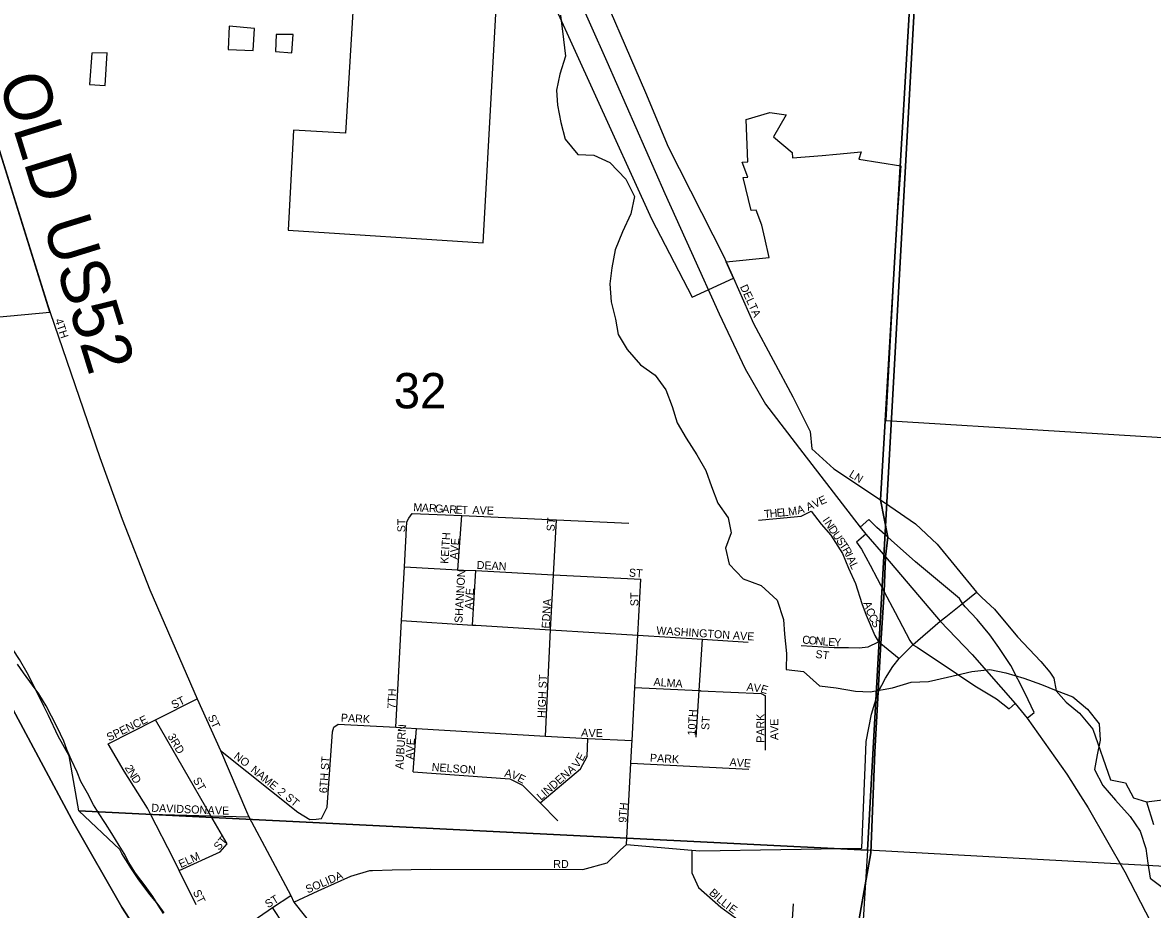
# Model space of a CAD drawing. Extents: x 0 to 34, y 0 to 22.
# Drawn here: x 3.579 to 4.916, y 15.917 to 16.966 of the extents above; entities that cross this region are included whole.
import ezdxf

# ---------------------------------------------------------------- set-up
doc = ezdxf.new("R2010")
doc.units = 0
for name, color, linetype in [('GM_X_City_Street', 7, 'Continuous'), ('GM_X_City_Street_Text', 7, 'Continuous'), ('GM_X_Corporation', 7, 'Continuous'), ('GM_X_County', 7, 'Continuous'), ('GM_X_County_Road', 7, 'Continuous'), ('GM_X_County_Road_Text', 7, 'Continuous'), ('GM_X_Interchange_Ramps', 7, 'Continuous'), ('GM_X_Major_River', 7, 'Continuous'), ('GM_X_Minor_River', 7, 'Continuous'), ('GM_X_Section', 7, 'Continuous'), ('GM_X_Section_Text', 7, 'Continuous'), ('GM_X_Township', 7, 'Continuous'), ('GM_X_US_Route', 7, 'Continuous')]:
    doc.layers.add(name, color=color, linetype=linetype)

msp = doc.modelspace()

# ---------------------------------------------------------------- linework, layer by layer
at = {"layer": 'GM_X_City_Street'}
for points in [[(4.4171, 16.6712), (4.4203, 16.6641), (4.444, 16.6102), (4.4906, 16.5234), (4.5111, 16.4824), (4.513, 16.4617), (4.5391, 16.4381), (4.5943, 16.4014), (4.6054, 16.394), (4.6357, 16.3731), (4.6611, 16.3492), (4.7078, 16.2921)], [(3.6089, 16.6314), (3.6115, 16.6232), (3.6703, 16.4516), (3.6969, 16.3788), (3.7295, 16.2949), (3.7856, 16.1658), (3.8131, 16.1047), (3.844, 16.0324)], [(4.0236, 16.191), (4.0236, 16.1911), (4.0273, 16.2587), (4.0308, 16.3221), (4.0338, 16.3753), (4.0361, 16.3799), (4.0399, 16.3855)], [(4.0399, 16.3855), (4.0794, 16.3837), (4.0794, 16.3837)], [(4.0794, 16.3837), (4.0987, 16.3829), (4.2108, 16.3779), (4.2965, 16.374)], [(4.094, 16.3188), (4.0987, 16.3829)], [(4.4497, 16.3775), (4.471, 16.3795)], [(4.471, 16.3795), (4.5002, 16.3823), (4.5123, 16.388)], [(4.5123, 16.388), (4.5241, 16.3729), (4.5352, 16.3595), (4.5491, 16.338), (4.5564, 16.3208), (4.5647, 16.3025), (4.5722, 16.2788), (4.5773, 16.265), (4.5876, 16.2408), (4.5917, 16.2336), (4.5946, 16.2313), (4.6163, 16.2137)], [(4.2036, 16.2475), (4.2072, 16.3128), (4.2108, 16.3779)], [(4.7142, 16.2859), (4.7289, 16.2719), (4.7564, 16.2394), (4.784, 16.21), (4.7944, 16.1975), (4.7992, 16.1905), (4.8021, 16.1756), (4.8137, 16.1619), (4.8296, 16.149), (4.8455, 16.13), (4.8663, 16.0699), (4.8842, 16.0666), (4.8936, 16.0489), (4.909, 16.0441), (4.9279, 16.0462), (4.9395, 16.0544), (4.958, 16.0642), (4.9762, 16.0851), (4.9804, 16.1117), (4.9849, 16.1577), (4.9906, 16.174), (5.0084, 16.2067), (5.094, 16.3278), (5.0961, 16.3307)], [(4.0308, 16.3221), (4.094, 16.3188), (4.1007, 16.3184)], [(4.1007, 16.3184), (4.1007, 16.3184), (4.1153, 16.3177), (4.2072, 16.3128), (4.3105, 16.3074)], [(4.1112, 16.2533), (4.1153, 16.3177)], [(4.2999, 16.1113), (4.3002, 16.1166), (4.3036, 16.1793), (4.3069, 16.2412), (4.3105, 16.3074)], [(4.6913, 16.2786), (4.7078, 16.2921), (4.7142, 16.2859)], [(4.6714, 16.2631), (4.6913, 16.2786)], [(4.5764, 16.0946), (4.5772, 16.1154), (4.5834, 16.1478), (4.5915, 16.174), (4.6002, 16.1905), (4.6087, 16.2042), (4.6163, 16.2137), (4.6283, 16.2261), (4.6326, 16.2298), (4.6648, 16.2579), (4.6714, 16.2631)], [(4.0273, 16.2587), (4.1112, 16.2533), (4.115, 16.2531), (4.1152, 16.2531)], [(4.1152, 16.2531), (4.2036, 16.2475), (4.3069, 16.2412), (4.3835, 16.2365), (4.4374, 16.2332)], [(4.1977, 16.1219), (4.2036, 16.2475)], [(4.3761, 16.1207), (4.3796, 16.1757), (4.3835, 16.2365)], [(4.5561, 16.2266), (4.5691, 16.2265), (4.5794, 16.2275), (4.5917, 16.2336)], [(4.5004, 16.2289), (4.5393, 16.2267), (4.5561, 16.2266)], [(4.0204, 16.1322), (4.0236, 16.191)], [(4.3036, 16.1793), (4.3796, 16.1757), (4.3811, 16.1757), (4.3812, 16.1756)], [(3.6802, 16.1128), (3.7361, 16.1409), (3.7856, 16.1658)], [(4.3812, 16.1756), (4.4529, 16.1722), (4.4582, 16.1695)], [(4.4582, 16.1053), (4.4582, 16.1695)], [(3.8018, 16.0274), (3.7361, 16.1409)], [(3.9263, 16.0236), (3.9328, 16.0242), (3.9394, 16.0375), (3.9458, 16.1267), (3.9474, 16.1324)], [(3.9474, 16.1324), (3.9523, 16.1361), (4.0204, 16.1322), (4.0451, 16.1307), (4.1977, 16.1219), (4.2479, 16.119), (4.3002, 16.1166)], [(4.0411, 16.0795), (4.0451, 16.1307)], [(3.7844, 15.9219), (3.7643, 15.9626), (3.7574, 15.9766), (3.7303, 16.0295), (3.7266, 16.0366), (3.6991, 16.0803), (3.6802, 16.1128)], [(4.1915, 16.0427), (4.2391, 16.0832), (4.2469, 16.0976), (4.2479, 16.119)], [(3.8131, 16.1047), (3.9048, 16.0318), (3.9187, 16.0229), (3.9263, 16.0236)], [(4.2936, 15.9936), (4.2988, 16.0898), (4.2999, 16.1113), (4.2999, 16.1113)], [(3.9928, 15.9628), (4.0161, 15.9637), (4.0611, 15.9641), (4.2417, 15.964), (4.2708, 15.9716), (4.286, 15.9868), (4.2936, 15.9936), (4.3709, 15.9869), (4.3803, 15.986), (4.5722, 15.9893), (4.5764, 16.0946)], [(4.2988, 16.0898), (4.4385, 16.0827)], [(4.0411, 16.0795), (4.1555, 16.0713), (4.1706, 16.0639), (4.1915, 16.0427), (4.2122, 16.0216)], [(3.844, 16.0324), (3.8466, 16.0261), (3.8963, 15.9332), (3.8997, 15.9253)], [(4.909, 16.0441), (4.9172, 16.0171)], [(3.7303, 16.0295), (3.8018, 16.0274), (3.8466, 16.0261)], [(3.8209, 15.9944), (3.8018, 16.0274)], [(3.7643, 15.9626), (3.8125, 15.9847), (3.8209, 15.9944)], [(4.3709, 15.9869), (4.3707, 15.96), (4.3788, 15.9425), (4.4051, 15.9194), (4.4355, 15.8973), (4.4532, 15.8892), (4.4727, 15.8878), (4.4889, 15.8866), (4.5222, 15.8842), (4.5644, 15.8812), (4.5676, 15.8809)], [(3.8997, 15.9253), (3.9286, 15.9388), (3.9673, 15.9559), (3.9898, 15.9626), (3.9928, 15.9628)], [(3.8147, 15.8773), (3.8747, 15.9191), (3.8963, 15.9332)], [(3.8997, 15.9253), (3.9381, 15.877), (3.9864, 15.8247), (4.0329, 15.7727), (4.0682, 15.7327), (4.1153, 15.6817), (4.1747, 15.6187), (4.2308, 15.5607), (4.2604, 15.5348), (4.3071, 15.4929), (4.3427, 15.4647), (4.4074, 15.4185), (4.4485, 15.3898), (4.5393, 15.3267), (4.6081, 15.2788), (4.668, 15.2381), (4.7235, 15.1974), (4.7623, 15.1671)], [(4.1954, 15.5228), (4.1384, 15.584), (4.0776, 15.6526), (4.0321, 15.7008), (3.994, 15.746), (3.9551, 15.8022), (3.9135, 15.8599), (3.8747, 15.9191)], [(4.4889, 15.8866), (4.4912, 15.9233)]]:
    msp.add_lwpolyline(points, dxfattribs=at)
at = {"layer": 'GM_X_Corporation'}
for points in [[(3.8462, 17.1086), (3.8428, 17.0214), (3.9716, 17.0124), (3.9612, 16.8357), (3.8995, 16.8391), (3.8931, 16.7208), (4.1239, 16.7058), (4.1451, 17.0913), (3.9294, 17.1039), (3.9291, 17.1108), (3.9182, 17.111), (3.9181, 17.1042)], [(3.8235, 16.9622), (3.8223, 16.9345), (3.8518, 16.9334), (3.8533, 16.9596)], [(3.878, 16.9323), (3.8977, 16.9308), (3.8989, 16.9525), (3.8791, 16.9525)], [(3.6766, 16.8919), (3.6789, 16.9308), (3.6609, 16.9304), (3.658, 16.8931)]]:
    msp.add_lwpolyline(points, close=True, dxfattribs=at)
for points in [[(4.1867, 17.0345), (4.3233, 16.7343), (4.3713, 16.6413), (4.4203, 16.6641), (4.4117, 16.6834), (4.4623, 16.6883), (4.4574, 16.7112), (4.4538, 16.7268), (4.447, 16.7445), (4.4413, 16.744), (4.4316, 16.783), (4.4373, 16.7835), (4.4305, 16.8012), (4.4371, 16.8017), (4.4353, 16.8516), (4.4631, 16.8601), (4.4827, 16.8573), (4.4677, 16.8312), (4.4896, 16.8128), (4.4901, 16.8062), (4.525, 16.8092), (4.5421, 16.8107), (4.5714, 16.8133), (4.5686, 16.8048), (4.6182, 16.797), (4.6155, 16.7584), (4.6129, 16.7216), (4.6006, 16.4954), (5.0117, 16.4703)], [(3.3651, 16.6008), (3.6113, 16.6236), (3.5258, 16.8961)], [(4.9409, 15.0109), (4.8087, 15.0697), (4.7171, 15.1027), (4.4484, 15.218), (4.2977, 15.3128), (4.1948, 15.3929), (4.1301, 15.4372), (3.9616, 15.5909), (3.8772, 15.6623), (3.7898, 15.775), (3.6963, 15.9193), (3.6399, 16.018), (3.4223, 16.4243)]]:
    msp.add_lwpolyline(points, dxfattribs=at)
at = {"layer": 'GM_X_County'}
msp.add_lwpolyline([(3.4223, 16.4243), (3.6399, 16.018), (3.6963, 15.9193), (3.7898, 15.775), (3.8772, 15.6623), (3.9616, 15.5909), (4.1301, 15.4372), (4.1948, 15.3929), (4.2977, 15.3128), (4.4484, 15.218), (4.53, 15.1758), (4.7171, 15.1027), (4.8087, 15.0697), (4.9409, 15.0109), (4.9836, 14.9934), (5.1229, 14.9601), (5.2411, 14.9222), (5.3493, 14.8892), (5.4549, 14.8608), (5.5492, 14.8433), (5.6098, 14.8494), (5.8119, 14.8141), (6.1284, 14.8081)], dxfattribs=at)
at = {"layer": 'GM_X_County_Road'}
for points in [[(4.2501, 17.0363), (4.3162, 16.8836), (4.343, 16.8193), (4.4087, 16.6894)], [(3.5297, 17.0209), (3.524, 16.9268), (3.5258, 16.8961), (3.6089, 16.6314)], [(4.4087, 16.6894), (4.4117, 16.6834), (4.4171, 16.6712)]]:
    msp.add_lwpolyline(points, dxfattribs=at)
at = {"layer": 'GM_X_Interchange_Ramps'}
for points in [[(4.6913, 16.2786), (4.6877, 16.2847), (4.6356, 16.3282), (4.6069, 16.3536), (4.6029, 16.3572), (4.5897, 16.3687), (4.5803, 16.3782), (4.57, 16.3692)], [(4.577, 16.361), (4.5659, 16.3513), (4.5715, 16.343), (4.5821, 16.3241), (4.5986, 16.2926), (4.6115, 16.2682), (4.6289, 16.2348), (4.6326, 16.2298)], [(4.7678, 16.1431), (4.7762, 16.1496), (4.7653, 16.1721), (4.7483, 16.2055), (4.7343, 16.2267), (4.7237, 16.2416), (4.7087, 16.26), (4.6942, 16.275), (4.6913, 16.2786)], [(4.6326, 16.2298), (4.6375, 16.2269), (4.6841, 16.1959), (4.7058, 16.1812), (4.7316, 16.1659), (4.7463, 16.1542), (4.7536, 16.1606)]]:
    msp.add_lwpolyline(points, dxfattribs=at)
at = {"layer": 'GM_X_Major_River'}
msp.add_lwpolyline([(3.7456, 15.9118), (3.7392, 15.9217), (3.7332, 15.9319), (3.7241, 15.9444), (3.7124, 15.9596), (3.7048, 15.9721), (3.6991, 15.9828), (3.6931, 15.9923), (3.6844, 16.0067), (3.6768, 16.0185), (3.6689, 16.031), (3.6629, 16.0405), (3.6557, 16.0541), (3.6477, 16.0682), (3.6436, 16.0792), (3.6368, 16.0932), (3.6311, 16.1058), (3.6277, 16.116), (3.6198, 16.1323), (3.613, 16.1456), (3.6069, 16.1578), (3.5982, 16.1718), (3.5907, 16.1821), (3.5801, 16.1969), (3.5729, 16.2071)], dxfattribs=at)
at = {"layer": 'GM_X_Minor_River'}
msp.add_lwpolyline([(4.2155, 16.9753), (4.2192, 16.9464), (4.2214, 16.9266), (4.2145, 16.9053), (4.2106, 16.8863), (4.212, 16.8688), (4.2157, 16.8483), (4.221, 16.8285), (4.236, 16.8102), (4.255, 16.8094), (4.2739, 16.801), (4.2927, 16.7811), (4.3032, 16.7606), (4.2986, 16.74), (4.2887, 16.7188), (4.2803, 16.6975), (4.2764, 16.6763), (4.274, 16.6573), (4.2755, 16.636), (4.2807, 16.6154), (4.2836, 16.5972), (4.2942, 16.5796), (4.31, 16.5613), (4.3274, 16.5491), (4.3402, 16.5316), (4.3477, 16.5118), (4.3536, 16.4928), (4.3642, 16.4745), (4.377, 16.4547), (4.3875, 16.4364), (4.3942, 16.4174), (4.4017, 16.3976), (4.4138, 16.3801), (4.4175, 16.3626), (4.4106, 16.3444), (4.4151, 16.3254), (4.4316, 16.3078), (4.4528, 16.3002), (4.4717, 16.2826), (4.4792, 16.2598), (4.4806, 16.2423), (4.4828, 16.2195), (4.4827, 16.2005), (4.5031, 16.1982), (4.522, 16.1814), (4.5417, 16.1791), (4.5644, 16.1752), (4.5818, 16.1744), (4.6083, 16.1788), (4.6303, 16.1856), (4.6508, 16.1863), (4.6735, 16.1915), (4.7023, 16.1983), (4.7236, 16.2005), (4.7425, 16.1966), (4.7637, 16.1905), (4.7848, 16.1828), (4.8022, 16.1759), (4.8219, 16.1682), (4.8392, 16.1537), (4.8528, 16.1362), (4.8542, 16.1172), (4.8504, 16.0998), (4.8473, 16.0823), (4.8571, 16.0633), (4.8721, 16.0458), (4.8895, 16.0267), (4.9015, 16.0092), (4.9082, 15.9887), (4.9104, 15.9712), (4.9134, 15.9537), (4.9338, 15.9384)], dxfattribs=at)
at = {"layer": 'GM_X_Section'}
for points in [[(3.5285, 17.0826), (4.636, 17.0167), (4.5788, 15.9866), (3.6453, 16.0334), (3.634, 16.0986), (3.6211, 16.1217), (3.6094, 16.1463), (3.6041, 16.1573), (3.595, 16.1759), (3.5844, 16.1967), (3.5753, 16.2123), (3.5678, 16.224), (3.559, 16.2373), (3.5496, 16.2517), (3.5405, 16.2699), (3.5348, 16.2794), (3.5261, 16.2919), (3.4765, 16.3344)], [(4.636, 17.0167), (5.7237, 16.9481), (5.6567, 15.9275), (4.5788, 15.9866)]]:
    msp.add_lwpolyline(points, close=True, dxfattribs=at)
msp.add_lwpolyline([(3.7464, 15.9125), (3.7392, 15.9223), (3.7297, 15.9341), (3.7165, 15.9515), (3.7078, 15.9648), (3.701, 15.9754), (3.6964, 15.983), (3.6938, 15.9875), (3.6453, 16.0334), (4.5788, 15.9866), (4.5286, 15.1803)], dxfattribs=at)
at = {"layer": 'GM_X_Township'}
for points in [[(4.6299, 17.0103), (4.5943, 16.4014), (4.6029, 16.3572), (4.6, 16.334), (4.5986, 16.2926), (4.5946, 16.2313), (4.5919, 16.1816), (4.5915, 16.174), (4.5876, 16.1027), (4.5828, 15.9836), (4.5644, 15.8812), (4.5608, 15.816), (4.5526, 15.6787), (4.5511, 15.6533), (4.5478, 15.5982), (4.5393, 15.3267), (4.53, 15.1758), (4.7171, 15.1027), (4.8087, 15.0697), (4.9409, 15.0109)], [(4.5644, 15.8812), (4.5828, 15.9836), (4.5876, 16.1027), (4.5915, 16.174), (4.5919, 16.1816), (4.5946, 16.2313), (4.5986, 16.2926), (4.6, 16.334), (4.6029, 16.3572), (4.5943, 16.4014), (4.6299, 17.0103)], [(3.4223, 16.4243), (3.6399, 16.018), (3.6963, 15.9193), (3.7898, 15.775)]]:
    msp.add_lwpolyline(points, dxfattribs=at)
at = {"layer": 'GM_X_US_Route'}
for points in [[(3.7496, 18.1784), (3.7599, 18.1503), (3.8059, 18.0295), (3.8644, 17.8742), (3.8936, 17.7971), (3.9933, 17.5496), (4.0789, 17.3466), (4.1735, 17.1378), (4.2703, 16.9203), (4.3388, 16.7642), (4.3703, 16.6944)], [(4.3703, 16.6944), (4.4031, 16.6215), (4.4341, 16.5566), (4.4582, 16.5149), (4.5024, 16.4573)], [(4.5024, 16.4573), (4.57, 16.3692), (4.577, 16.361), (4.6, 16.334), (4.6648, 16.2579), (4.7025, 16.2183), (4.7536, 16.1606), (4.7678, 16.1431), (4.8148, 16.0767), (4.8309, 16.0512)], [(4.8309, 16.0512), (4.8399, 16.0369), (4.8834, 15.9611), (4.9139, 15.9017), (4.9358, 15.8635), (4.9701, 15.8096), (4.9839, 15.791), (5.0221, 15.7512), (5.0502, 15.7273), (5.0757, 15.7119), (5.1054, 15.697), (5.1373, 15.6832), (5.2153, 15.654), (5.2817, 15.6306), (5.3172, 15.6152), (5.3507, 15.5945), (5.4554, 15.4954), (5.5676, 15.398), (5.6488, 15.3249)]]:
    msp.add_lwpolyline(points, dxfattribs=at)

# ---------------------------------------------------------------- texts
at = {"layer": 'GM_X_City_Street_Text'}
for s, rotation, p in [('DELTA', 294.3422, (4.4276, 16.6538)), ('4TH', 288.4418, (3.6169, 16.6144)), ('LN', 327.9928, (4.5561, 16.4295)), ('E', 24.7745, (4.5238, 16.3951)), ('M', 356.6941, (4.0411, 16.3882)), ('A', 356.696, (4.0511, 16.3876)), ('R', 356.6925, (4.0595, 16.3871)), ('G', 356.696, (4.0669, 16.3867)), ('A', 356.696, (4.0753, 16.3862)), ('R', 356.6925, (4.0836, 16.3857)), ('E', 357.1073, (4.0911, 16.3853)), ('T', 359.2995, (4.0982, 16.3849)), ('AVE', 358.0247, (4.1111, 16.3848)), ('M', 8.6203, (4.4856, 16.3826)), ('A', 15.0819, (4.4966, 16.3844)), ('A', 24.7745, (4.5086, 16.3881)), ('V', 24.7745, (4.5162, 16.3916)), ('ST', 86.4256, (4.2084, 16.364)), ('T', 5.3894, (4.4568, 16.3799)), ('H', 5.3894, (4.4634, 16.3805)), ('E', 5.3894, (4.4717, 16.3813)), ('L', 5.3894, (4.4784, 16.3819)), ('I', 303.9431, (4.525, 16.3774)), ('ST', 90, (4.0318, 16.3631)), ('N', 303.9227, (4.5274, 16.3739)), ('D', 303.925, (4.532, 16.367)), ('KEITH', 85.9166, (4.0826, 16.3255)), ('AVE', 86.057, (4.0939, 16.3306)), ('U', 303.9251, (4.5367, 16.3601)), ('S', 303.9361, (4.5413, 16.3532)), ('T', 303.9155, (4.545, 16.3477)), ('R', 299.7562, (4.5486, 16.3423)), ('DEAN', 357.0643, (4.1161, 16.3198)), ('I', 295.1965, (4.5523, 16.3359)), ('A', 294.833, (4.554, 16.3322)), ('L', 294.778, (4.5575, 16.3246)), ('SHANNON', 86.6354, (4.0993, 16.2555)), ('ST', 356.4228, (4.2962, 16.3107)), ('AVE', 86.057, (4.1114, 16.2714)), ('ST', 90, (4.3076, 16.2756)), ('EDNA', 87.0659, (4.2026, 16.249)), ('A', 289.6134, (4.5736, 16.2795)), ('C', 291.3984, (4.5765, 16.2713)), ('C', 295.8926, (4.5795, 16.2636)), ('S', 296.5582, (4.5829, 16.2567)), ('WASHINGTON AVE', 356.3669, (4.3287, 16.2423)), ('C', 355.0635, (4.5012, 16.2315)), ('O', 355.057, (4.5087, 16.2308)), ('N', 355.0689, (4.517, 16.2301)), ('L', 355.0616, (4.5253, 16.2294)), ('E', 355.7329, (4.532, 16.2288)), ('Y', 359.0483, (4.5393, 16.2283)), ('ST', 352.8767, (4.5167, 16.2145)), ('HIGH ST', 87.876, (4.1976, 16.1431)), ('ALMA', 355.8151, (4.3253, 16.1815)), ('A', 353.4186, (4.4353, 16.1757)), ('V', 353.4199, (4.4436, 16.1747)), ('E', 342.7503, (4.4514, 16.1739)), ('ST', 26.565, (3.7577, 16.1538)), ('7TH', 87.7106, (4.0201, 16.154)), ('10TH', 86.4256, (4.3751, 16.1223)), ('SPENCE', 26.0749, (3.6811, 16.1155)), ('ST', 295.017, (3.7977, 16.1446)), ('PARK', 356.9057, (3.9553, 16.139)), ('ST', 86.4256, (4.3914, 16.1288)), ('PARK', 90, (4.4568, 16.1139)), ('AVE', 90, (4.4731, 16.1172)), ('AUBURN', 86.1236, (4.0293, 16.0822)), ('A', 355.3167, (4.2396, 16.1215)), ('V', 359.2728, (4.2486, 16.1208)), ('E', 359.9999, (4.2571, 16.1207)), ('3RD', 300.5801, (3.7501, 16.1215)), ('AVE', 86.057, (4.0414, 16.0939)), ('NO', 323.1285, (3.8279, 16.0961)), ('E', 62.6816, (4.2418, 16.0914)), ('PARK', 356.906, (4.3211, 16.0915)), ('2', 299.6597, (3.6994, 16.0846)), ('NAME', 321.1172, (3.848, 16.0803)), ('6TH ST', 86.188, (3.9393, 16.054)), ('NELSON', 355.8402, (4.0628, 16.0807)), ('A', 38.1704, (4.2275, 16.0761)), ('V', 53.3567, (4.2359, 16.0833)), ('AVE', 355.9142, (4.4153, 16.0865)), ('N', 302.7536, (3.7025, 16.079)), ('D', 303.0449, (3.7071, 16.072)), ('ST', 299.7432, (3.7801, 16.0698)), ('A', 348.0753, (4.1486, 16.074)), ('V', 336.0064, (4.1562, 16.0725)), ('E', 333.435, (4.1637, 16.0691)), ('LINDEN', 41.0806, (4.1924, 16.0452)), ('2', 315.0068, (3.8798, 16.0551)), ('ST', 320.1969, (3.8889, 16.0478)), ('DAVIDSON', 357.6467, (3.7311, 16.0323)), ('A', 355.2182, (3.7974, 16.0298)), ('V', 359.6386, (3.8065, 16.0291)), ('E', 359.9985, (3.8149, 16.029)), ('9TH', 85.4285, (4.2934, 16.019)), ('ST', 50.1886, (3.8113, 15.9859)), ('ELM', 24.7772, (3.7661, 15.9655)), ('RD', 0, (4.2069, 15.9657)), ('SOLIDA', 23.0516, (3.9162, 15.9355)), ('ST', 296.5647, (3.7801, 15.9372)), ('B', 318.2418, (4.3906, 15.9352)), ('ST', 31.6151, (3.8693, 15.9179)), ('I', 318.2507, (4.3962, 15.9302)), ('L', 318.3975, (4.3993, 15.9274)), ('L', 321.1059, (4.4047, 15.9227)), ('I', 323.045, (4.4101, 15.9183)), ('E', 323.9242, (4.4136, 15.9157))]:
    msp.add_text(s, height=0.00947, rotation=rotation, dxfattribs=at).set_placement(p)
at = {"layer": 'GM_X_County_Road_Text'}
msp.add_text('OLD US52', height=0.05682, rotation=287.2024, dxfattribs=at).set_placement((3.5499, 16.898))
at = {"layer": 'GM_X_Section_Text'}
msp.add_text('32', height=0.04186, rotation=0, dxfattribs=at).set_placement((4.0181, 16.5098))

doc.saveas('drawing.dxf')
